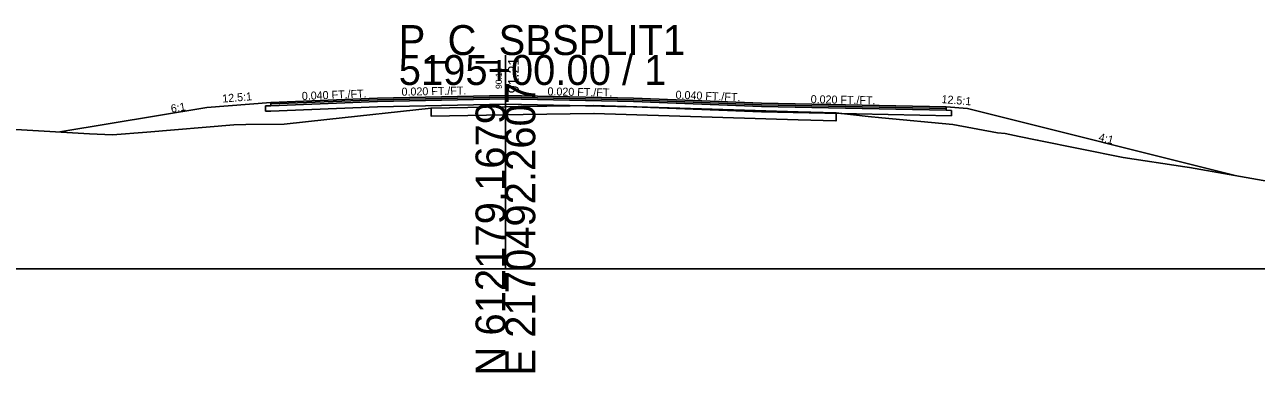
# Model space of a CAD drawing. Extents: x -26 to 1303, y -3010 to 12023.
# Drawn here: x 104.9 to 220.4, y 11990.3 to 12022.8 of the extents above; entities that cross this region are included whole.
import ezdxf

# ---------------------------------------------------------------- set-up
doc = ezdxf.new("R2010")
doc.units = 0
for name, color, linetype in [('RD_GPK_XS_Cell', 7, 'Continuous'), ('RD_XS_Base', 7, 'Continuous'), ('RD_XS_ExGround', 7, 'Continuous'), ('RD_XS_ExPaveRet', 7, 'Continuous'), ('RD_XS_Greenside', 7, 'Continuous'), ('RD_XS_Pave', 7, 'Continuous'), ('RD_XS_PaveOvlay_CP', 7, 'Continuous'), ('RD_XS_TieSlope', 7, 'Continuous'), ('RD_XS_TX_Elev_EX', 7, 'Continuous'), ('RD_XS_TX_Elev_PR', 7, 'Continuous'), ('RD_XS_TX_ShdSlope', 7, 'Continuous'), ('RD_XS_TX_Slope', 7, 'Continuous')]:
    doc.layers.add(name, color=color, linetype=linetype)

msp = doc.modelspace()

# ---------------------------------------------------------------- linework, layer by layer
at = {"layer": 'RD_GPK_XS_Cell'}
for p, q in [((150, 12000), (150, 12020)), ((0, 12000), (150, 12000)), ((150, 12000), (300, 12000))]:
    msp.add_line(p, q, dxfattribs=at)
at = {"layer": 'RD_XS_Base'}
for p, q in [((138, 12015.66), (150, 12015.9)), ((150, 12015.9), (150, 12016.06)), ((150, 12016.06), (150, 12015.4)), ((150, 12015.9), (150, 12015.9)), ((162, 12015.66), (150, 12015.9)), ((150, 12015.9), (150, 12015.9)), ((150, 12015.9), (150, 12015.4)), ((127.5, 12015.24), (128, 12015.26)), ((127.5, 12014.74), (127.5, 12015.24)), ((127.5, 12015.24), (127.5, 12015.24)), ((128, 12014.76), (127.5, 12014.74)), ((127.5, 12014.74), (127.5, 12014.74)), ((127.5, 12014.74), (127.5, 12014.74)), ((128, 12015.26), (138, 12015.66)), ((128, 12015.26), (128, 12015.26)), ((138, 12015.16), (128, 12014.76)), ((128, 12014.76), (128, 12014.76)), ((136, 12015.58), (136, 12015.58)), ((136, 12015.08), (136, 12015.08)), ((150, 12015.4), (138, 12015.16)), ((150, 12015.4), (150, 12015.4)), ((150, 12015.4), (162, 12015.16)), ((150, 12015.4), (150, 12015.4)), ((174, 12015.18), (162, 12015.66)), ((162, 12015.66), (162, 12015.66)), ((162, 12015.16), (162, 12015.16)), ((162, 12015.16), (174, 12014.68)), ((191.32, 12014.83), (174, 12015.18)), ((174, 12015.18), (174, 12015.18)), ((174, 12014.68), (174, 12014.68)), ((174, 12014.68), (191.82, 12014.32)), ((191.82, 12014.82), (191.32, 12014.83)), ((191.32, 12014.83), (191.32, 12014.83)), ((191.82, 12014.32), (191.82, 12014.82)), ((191.82, 12014.82), (191.82, 12014.82)), ((191.82, 12014.32), (191.82, 12014.32)), ((191.82, 12014.32), (191.82, 12014.32))]:
    msp.add_line(p, q, dxfattribs=at)
at = {"layer": 'RD_XS_ExGround'}
msp.add_lwpolyline([(96.15, 12013.51), (111.02, 12012.63), (113.17, 12012.52), (116.38, 12012.78), (124.55, 12013.47), (125.68, 12013.49), (129.27, 12013.54), (133.26, 12013.96), (143.03, 12015.03), (151.68, 12015.17), (158.3, 12015.28), (177.44, 12014.69), (180.98, 12014.58), (184.01, 12014.26), (185.29, 12014.12), (191.93, 12013.5), (196.13, 12012.73), (196.83, 12012.66), (198.15, 12012.38), (199.85, 12012.04), (207.92, 12010.42), (213.68, 12009.54), (214.13, 12009.46), (223.16, 12007.88)], dxfattribs=at)
at = {"layer": 'RD_XS_ExPaveRet'}
for points in [[(180.99, 12014.58), (180.99, 12013.83), (180.99, 12013.83), (180.98, 12013.83), (180.98, 12013.83), (177.44, 12013.94), (177.44, 12013.94), (158.3, 12014.53), (158.3, 12014.53), (151.68, 12014.42), (151.68, 12014.42), (143.03, 12014.28), (143.03, 12014.28), (143.03, 12015.03), (151.68, 12015.17), (151.68, 12015.17), (158.3, 12015.28), (158.3, 12015.28), (177.44, 12014.69), (177.44, 12014.69), (180.98, 12014.58), (180.98, 12014.58), (180.99, 12014.58)], [(180.98, 12014.58), (177.44, 12014.69), (158.3, 12015.28), (151.68, 12015.17), (143.03, 12015.03), (143.03, 12014.28), (151.68, 12014.42), (158.3, 12014.53), (177.44, 12013.94), (180.98, 12013.83), (180.99, 12013.83), (180.99, 12014.58), (180.98, 12014.58)]]:
    msp.add_lwpolyline(points, dxfattribs=at)
at = {"layer": 'RD_XS_Greenside'}
for p, q in [((122, 12015.09), (108.22, 12012.8)), ((193.32, 12014.99), (218.41, 12008.72))]:
    msp.add_line(p, q, dxfattribs=at)
at = {"layer": 'RD_XS_Pave'}
for p, q in [((138, 12015.97), (128, 12015.57)), ((138, 12015.82), (128, 12015.42)), ((128, 12015.42), (138, 12015.82)), ((136, 12015.89), (136, 12015.89)), ((136, 12015.74), (136, 12015.74)), ((136, 12015.74), (136, 12015.74)), ((150, 12016.21), (138, 12015.97)), ((150, 12016.06), (138, 12015.82)), ((138, 12015.82), (150, 12016.06)), ((138, 12015.66), (150, 12015.9)), ((162, 12015.97), (150, 12016.21)), ((150, 12015.9), (150, 12016.06)), ((150, 12016.06), (162, 12015.82)), ((162, 12015.82), (150, 12016.06)), ((150, 12016.06), (150, 12016.06)), ((150, 12016.06), (150, 12015.9)), ((150, 12015.9), (150, 12015.9)), ((150, 12015.9), (150, 12015.9)), ((150, 12015.9), (150, 12015.9)), ((150, 12015.9), (162, 12015.66)), ((174, 12015.49), (162, 12015.97)), ((162, 12015.97), (162, 12015.97)), ((162, 12015.82), (162, 12015.82)), ((162, 12015.82), (174, 12015.34)), ((174, 12015.34), (162, 12015.82)), ((162, 12015.82), (162, 12015.82)), ((128, 12015.26), (138, 12015.66)), ((128, 12015.57), (128, 12015.57)), ((128, 12015.57), (128, 12015.42)), ((128, 12015.42), (128, 12015.42)), ((128, 12015.42), (128, 12015.26)), ((128, 12015.42), (128, 12015.42)), ((128, 12015.42), (128, 12015.42)), ((128, 12015.26), (128, 12015.26)), ((128, 12015.26), (128, 12015.26)), ((136, 12015.58), (136, 12015.58)), ((162, 12015.66), (162, 12015.66)), ((162, 12015.66), (174, 12015.18)), ((191.32, 12015.15), (174, 12015.49)), ((174, 12015.49), (174, 12015.49)), ((174, 12015.34), (174, 12015.34)), ((174, 12015.34), (191.32, 12014.99)), ((191.32, 12014.99), (174, 12015.34)), ((174, 12015.34), (174, 12015.34)), ((174, 12015.18), (174, 12015.18)), ((174, 12015.18), (191.32, 12014.83)), ((191.32, 12014.99), (191.32, 12015.15)), ((191.32, 12015.15), (191.32, 12015.15)), ((191.32, 12014.99), (191.32, 12014.99)), ((191.32, 12014.99), (191.32, 12014.99)), ((191.32, 12014.83), (191.32, 12014.99)), ((191.32, 12014.99), (191.32, 12014.99)), ((191.32, 12014.83), (191.32, 12014.83)), ((191.32, 12014.83), (191.32, 12014.83))]:
    msp.add_line(p, q, dxfattribs=at)
at = {"layer": 'RD_XS_PaveOvlay_CP'}
for p, q in [((138, 12015.97), (128, 12015.57)), ((136, 12015.89), (136, 12015.89)), ((150, 12016.21), (138, 12015.97)), ((162, 12015.97), (150, 12016.21)), ((174, 12015.49), (162, 12015.97)), ((162, 12015.97), (162, 12015.97)), ((128, 12015.57), (128, 12015.57)), ((191.32, 12015.15), (174, 12015.49)), ((174, 12015.49), (174, 12015.49)), ((191.32, 12015.15), (191.32, 12015.15))]:
    msp.add_line(p, q, dxfattribs=at)
at = {"layer": 'RD_XS_TieSlope'}
for p, q in [((128, 12015.57), (122, 12015.09)), ((191.32, 12015.15), (193.32, 12014.99))]:
    msp.add_line(p, q, dxfattribs=at)

# ---------------------------------------------------------------- texts
at = {"layer": 'RD_GPK_XS_Cell'}
for s, p in [('P_C_SBSPLIT1', (140, 12020)), ('5195+00.00 / 1', (140, 12017.2))]:
    msp.add_text(s, height=2.8, dxfattribs=at).set_placement(p)
for s, p in [('E 2170492.2607', (152.8, 11990)), ('N 612179.1679', (150, 11990))]:
    msp.add_text(s, height=2.8, rotation=90, dxfattribs=at).set_placement(p)
at = {"layer": 'RD_XS_TX_Elev_EX'}
msp.add_text('90.14', height=0.6, rotation=90, dxfattribs=at).set_placement((149.68, 12016.82))
at = {"layer": 'RD_XS_TX_Elev_PR'}
msp.add_text('91.21', height=1, rotation=90, dxfattribs=at).set_placement((151.25, 12016.41))
at = {"layer": 'RD_XS_TX_ShdSlope'}
for rotation, p in [(4.5739, (123.49, 12015.55)), (355.4261, (190.86, 12015.51))]:
    msp.add_text('12.5:1', height=0.75, rotation=rotation, dxfattribs=at).set_placement(p)
at = {"layer": 'RD_XS_TX_Slope'}
for s, rotation, p in [('0.020 FT./FT.', 1.1458, (140.27, 12016.19)), ('0.020 FT./FT.', 358.8542, (153.94, 12016.23)), ('0.040 FT./FT.', 2.2906, (130.93, 12015.79)), ('0.040 FT./FT.', 357.7094, (165.94, 12015.92)), ('0.020 FT./FT.', 358.8542, (178.61, 12015.5)), ('6:1', 9.4623, (118.7, 12014.6)), ('4:1', 345.9638, (205.55, 12011.99))]:
    msp.add_text(s, height=0.75, rotation=rotation, dxfattribs=at).set_placement(p)

doc.saveas('drawing.dxf')
